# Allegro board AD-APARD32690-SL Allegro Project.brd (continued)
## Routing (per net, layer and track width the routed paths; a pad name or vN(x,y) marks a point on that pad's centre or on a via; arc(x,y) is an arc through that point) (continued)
GND_EARTH: length 68.5
  L2_GND w0.381: P1.1 4.83,41.01 ; P1.1 4.83,38.24 ; P1.1 6.21,39.62 ; P1.1 3.44,39.62
  L3_SIG w0.381: 4.83,38.24 P1.1 ; P1.1 3.44,39.62 ; P1.1 6.21,39.62 ; P1.1 4.83,41.01
  L4_GND w0.381: P1.1 4.83,41.01 ; P1.1 6.21,39.62 ; P1.1 3.44,39.62 ; P1.1 4.83,38.24
  L5_PWR w0.381: 4.83,38.24 P1.1 ; P1.1 3.44,39.62 ; P1.1 4.83,41.01 ; P1.1 6.21,39.62
  L6_PWR w0.381: P1.1 4.83,41.01 ; P1.1 6.21,39.62 ; P1.1 4.83,38.24 ; P1.1 3.44,39.62
  L7_GND w0.381: P1.1 6.21,39.62 ; P1.1 4.83,41.01 ; P1.1 4.83,38.24 ; P1.1 3.44,39.62
  L8_SIG w0.381: 4.83,38.24 P1.1 ; P1.1 3.44,39.62 ; P1.1 6.21,39.62 ; P1.1 4.83,41.01
  L9_GND w0.381: 4.83,38.24 P1.1 ; P1.1 6.21,39.62 ; P1.1 4.83,41.01 ; P1.1 3.44,39.62
  BOTTOM w0.381: P1.1 6.21,39.62 ; P1.1 4.83,41.01 ; P1.1 3.44,39.62 ; P1.1 4.83,38.24 ; C104.2 10.05,40.41 ; C104.2 8.45,41.24 ; C104.2 6.85,40.41 ; C106.2 10.05,50.27 ; C106.2 8.45,49.44 ; C106.2 6.85,50.27
  BOTTOM w0.762: C106.2 v6(8.45,51.5) ; C104.2 v6(8.45,39.18)
  BOTTOM w1.016: C105.2 35.49,36.68 C103.2 35.64,40.59 R147.2
GND_ISO: length 2.5
  TOP w1.016: P11.1 P11.2
VDD_1P1_D: length 108.5
  TOP w0.127: v1(102.17,33.18) 102,33.01 U1.H12
  L8_SIG w0.508: v6(31.18,3.37) 31.69,2.86 40.83,2.86 42.35,4.38 100.01,4.38 102.81,7.18 102.81,24.89 102.17,25.53 v1(102.17,33.18)
  BOTTOM w0.381: 30.23,5.17 C36.1 ; C36.1 31.24,5.17 ; C36.1 30.73,4.64 ; C25.1 103.07,33.18 v1(102.17,33.18) ; 28.94,5.15 C34.2 ; C34.2 30.11,5.15 ; C34.2 29.53,4.61 ; 32.26,3.44 R124.1 31.64,4.01
  vias: v6(30.48,4.06) v6(30.48,3.37) v6(31.18,4.06)
VDD_3P3_D: length 69
  TOP w0.102: 99.31,30.73 U1.B11
  TOP w0.127: U1.D1 100.6,25.41 100.17,24.99 ; 98.95,27.7 U1.A4
  TOP w0.152: 100.3,32.92 100.6,32.62 U1.D12 ; v1(105.09,25.21) 105.09,25.53 104.01,26.61 104.01,26.99 103.65,27.35 U1.M3
  TOP w0.254: C42.1 62.42,45.88 Q4.2 ; v1(97.89,26.64) 98.95,27.7 ; R168.2 v1(62.79,41.08)
  TOP w0.381: 147.51,19.56 C118.1 ; C118.1 148.05,20.07 ; C118.1 148.05,19.05 ; DS4.A v1(62.93,28.08) ; C116.1 146.85,20.07 ; C116.1 146.85,19.05 ; C116.1 147.38,19.56 ; 146.87,17.83 C115.2 ; C115.2 147.41,18.41 ; C115.2 146.87,19 ; C86.1 146.87,21.29 ; C86.1 146.87,20.12 ; C86.1 147.41,20.7 ; C42.1 v1(62.36,46.55) ; S4.3B v1(112.14,1.52) ; S4.2B v1(113.41,1.52) ; 147.48,20.7 C89.1 ; C89.1 148.03,20.12 ; C89.1 148.03,21.29 ; 147.48,18.41 C117.2 ; C117.2 148.03,19 ; C117.2 148.03,17.83 ; v1(100.33,35.05) 100.33,34.55 C27.1 100.33,34.54 100.33,33.43 C70.1 100.3,32.92 ; R126.2 v1(66.29,42.1) ; v6(58.1,33.76) E6.1 ; 100.17,24.99 C20.1 100.2,24.36 C19.2 100.08,23.12 v1(100.08,22.67) ; 114.68,2.48 v1(114.68,1.52) ; JP3.3 v6(138.81,39.45) ; S2.3 v1(118.65,15.28) ; D5.3 v1(119.32,1.97) ; DS2.A v1(127.95,1.91) ; R136.1 v1(130.11,11.24) ; R132.1 v1(65.67,44.97) ; S2.4 v1(128.81,15.28) ; C67.1 98.08,30.73 99.31,30.73 ; R128.1 60.85,33.41 60.14,32.7 v6(59.25,32.7) ; v1(64.96,27.3) 64.96,27.96 DS3.A ; D5.1 v1(121.54,1.97) ; R133.1 v1(131.25,11.24) ; R120.1 v1(111.89,32.35)
  TOP w0.508: v6(141.22,43.69) R141.1 ; v1(65.85,37.65) 65.21,37.65 C69.1 C92.2 ; M1.9 146.9,21.62 ; C21.1 97.32,32.62 ; 97.32,32.62 C67.1 ; 97.32,32.62 v6(97.32,33.3) ; JP4.3 v6(138.42,1.96) ; v6(40.77,4.57) 40.77,4.81 JP2.3 ; M1.10 147.9,21.6 ; v6(141.22,46.23) R142.1
  L2_GND w0.127: 101.41,34.29 101.41,30.48 101.3,30.37 v2(101.3,30.15)
  L2_GND w0.254: v1(102.17,35.05) 101.41,34.29
  BOTTOM w0.254: U2.35 v1(65.85,37.65)
  BOTTOM w0.381: C26.1 103.44,36.17 C75.1 v1(102.17,35.05) ; C74.1 105.5,25.21 v1(105.09,25.21) ; v1(66.29,42.1) 66.04,42.35 R125.2
  BOTTOM w0.508: v1(97.89,26.64) 97.95,26.7 C66.1 C71.1 ; v6(56.13,44.07) 57,44.07 E5.1
  vias: v6(40.89,20.83) v6(40.89,20.19) v6(41.66,20.83) v6(41.66,20.19) v6(110.3,12.64) v6(111,12.64) v6(146.81,17.72) v6(146.81,17.08) v6(147.45,17.72) v6(147.45,17.08) v6(148.08,17.72) v6(148.08,17.08)
VDD_5P0: length 151.5
  TOP w0.254: 49.02,11.05 48.81,11.26 U4.15 ; U3.4 27.5,13.59 v1(27.3,13.4) 27.3,13.14 ; 27.3,13.14 27.36,13.09 U3.5 ; 27.3,13.14 v1(27.3,12.76) 27.48,12.59 U3.6 ; v1(31.5,16.13) 31.5,15.3 31.29,15.09 U3.16 ; U4.9 45.81,11.15 v6(46.04,10.92) 46.31,11.2 U4.10
  TOP w0.381: U9.4 58.49,11.8 ; C127.1 57.08,10.73 ; C127.1 56.55,10.22 ; C127.1 56.55,11.24 ; C126.2 57.12,9.53 ; C126.2 56.57,8.94 ; C126.2 56.57,10.11 ; U9.2 57.19,11.83 ; U9.1 56.54,11.85 ; C112.1 53.59,5.18 ; U9.3 57.84,11.82 ; JP3.1 v6(141.16,37.77) ; v1(58.94,9.15) 58.94,9.91 R170.1
  TOP w0.508: R13.2 v1(46.99,8.38) ; R173.2 58.04,5.33 57.21,6.16 v6(57.21,8.06) ; R16.2 v1(45.85,8.38) ; JP4.1 139.75,3.68 v6(141.1,3.68) ; R14.2 v1(48.13,8.38) ; R15.2 v1(49.28,8.38)
  TOP w0.762: 53.59,5.18 P2.5
  L3_SIG w0.762: v6(141.1,3.68) 140.46,4.32 62.18,4.32 58.43,8.06 v6(57.21,8.06)
  L6_PWR w0.762: v6(141.1,3.68) 139.06,5.71 139.06,33.59 141.16,35.69 v6(141.16,37.77)
  BOTTOM w0.508: v1(31.5,16.13) R17.1
  vias: v6(50.86,10.54) v6(50.86,9.91) v6(51.5,10.54) v6(51.5,9.91) v6(52.13,10.54) v6(52.13,9.91) v6(52.96,6.54) v6(52.96,5.84) v6(56.58,8.7) v6(56.58,8.06) v6(57.21,8.7)
VDD_5P0_INT: length 10.5
  TOP w0.305: 49.31,18.03 49.31,19.61 JP1.1 ; 49.31,18.03 U4.1 ; 49.31,18.03 48.7,18.03 ; U4.2 48.81,17.93 48.7,18.03 ; 48.7,18.03 48.51,18.03 v6(48.32,17.84) 48.31,17.83 U4.3
  TOP w0.508: 21.02,12.19 20.57,11.75
  TOP w0.635: v6(20.57,11.43) v6(20.57,12.19) 21.65,12.19 R1.2 C1.2
  vias: v6(32.07,24.07) v6(32.07,23.43) v6(32.07,22.8) v6(32.7,24.07) v6(32.7,23.43) v6(32.7,22.8) v6(33.34,24.07) v6(33.34,23.43) v6(33.34,22.8) v6(49.21,18.48) v6(49.21,17.84)
VDDA_BB: length 4.8
  TOP w0.381: C29.2 106.61,30.23 v1(105.98,30.23)
  TOP w0.508: C29.2 C31.1
  L2_GND w0.127: v1(105.98,30.23) 104.9,30.23 104.48,29.8 v2(103.05,29.8)
VDDA_RF: length 5.8
  TOP w0.127: U1.M10 104.83,29.8 105.09,30.07
  TOP w0.254: 105.09,30.07 106.08,31.05
  TOP w0.381: 106.08,31.05 107.53,31.05 C30.2
  TOP w0.508: C30.2 C33.1
32KIN: length 6.2
  L2_GND w0.102: v3(103.05,30.15) v2(102.7,29.8)
  L3_SIG w0.089: v1(105.63,29.81) 105.38,29.56 104.01,29.56 103.42,30.15 v3(103.05,30.15)
  BOTTOM w0.127: v1(105.63,29.81) 105.92,29.81 106.24,29.5 106.58,29.5 C45.1 108.12,29.66 Y3.1
32KOUT: length 6.1
  L3_SIG w0.089: v1(105.63,29.31) 103.89,29.31 103.35,29.84 103,29.84 v3(102.7,30.15)
  BOTTOM w0.127: Y3.2 108.09,28.75 C53.1 106.57,28.92 106.01,28.92 v1(105.63,29.31)
ADC_IN0: length 4.5
  TOP w0.127: P3.1 67.88,4.13 68.96,4.13 69.34,4.51 R89.2
ADC_IN1: length 3.5
  TOP w0.127: R110.2 70.87,4.57 P3.2
ADC_IN2: length 3
  TOP w0.127: P3.3 72.39,3.56 R90.2
ADC_IN3: length 2.6
  TOP w0.127: R111.2 P3.4
ADC_IN4: length 2.6
  TOP w0.127: R91.2 P3.5
ADC_IN5: length 2.6
  TOP w0.127: R112.2 P3.6
ADC_IN6: length 2.6
  TOP w0.127: R92.2 P3.7
ADC_IN7: length 2.6
  TOP w0.127: R113.2 P3.8
ADIN1100_TS_TIMER_MS_SEL: length 18
  TOP w0.127: JP5.1 v1(141.17,18.11) ; JP6.1 v1(141.15,5.41)
  L3_SIG w0.089: v1(141.17,18.11) 141.17,5.44 v1(141.15,5.41)
ADIN1110_INT: length 44.7
  TOP w0.127: R56.1 80.74,15.4 v1(80.14,15.4) ; R168.1 61.79,40.33 v1(61.79,41.08)
  L3_SIG w0.089: v1(61.79,41.08) 62.17,40.7 66.23,40.7 67.56,39.37 67.56,17.91 71.06,14.41 79.15,14.41 v1(80.14,15.4)
  BOTTOM w0.127: U2.25 v1(61.79,41.08)
ADIN1110_LINK_ST: length 36.9
  TOP w0.127: v1(83.5,15.4) 84.1,15.4 R22.1
  BOTTOM w0.127: v1(83.5,15.4) 83.09,15.81 68.61,15.81 63.6,20.83 63.6,32.1 62.79,32.9 U2.4
ADIN1110_RESET: length 34.7
  TOP w0.127: v1(78.93,15.4) 80.52,16.99 R55.1
  BOTTOM w0.127: v1(78.93,15.4) 68.39,15.4 63.28,20.51 63.28,31.85 62.29,32.83 U2.5
ADIN1110_SPI_CFG1: length 64.4
  TOP w0.127: v1(112.14,13.53) R166.1
  BOTTOM w0.127: U2.37 66.22,36.65 67.79,35.08 67.79,23.4 72.58,18.61 78.71,18.61 79.63,17.68 83.47,17.68 86.77,14.38 104.55,14.38 105.41,13.53 v1(112.14,13.53)
ADIN1110_TS_CAPT: length 34.5
  TOP w0.127: R49.1 84.17,16.99 v1(83.5,16.99)
  BOTTOM w0.127: U2.40 65.43,35.15 65.6,34.99 65.6,21.84 70.1,17.34 83.15,17.34 v1(83.5,16.99)
ADIN1110_TS_TIMER_MS_SEL: length 33.8
  TOP w0.127: R29.1 v1(80.14,18.41)
  BOTTOM w0.127: U2.30 64.29,40.7 64.42,40.83 65.56,40.83 68.68,37.72 68.68,24.89 74.17,19.4 79.15,19.4 v1(80.14,18.41)
BLE_LDO_1V1: length 35.8
  TOP w0.508: v1(54.99,21.08) 54.98,21.07 JP11.3
  BOTTOM w0.508: E4.2 34.38,6.41 C39.1 35.4,7.54 C38.2 35.38,8.51 35.89,9.02 39.27,9.02 40.29,10.03 42.74,10.03 45.09,12.38 52.32,12.38 53.66,13.72 53.66,19.75 v1(54.99,21.08)
  BOTTOM w0.762: C37.2 34,4.55 E4.2
BLE_LDO_IN: length 90.9
  TOP w0.127: 103.06,31.31 102.7,30.94 U1.K12
  TOP w0.381: v6(103.89,41.59) 105.57,39.91 105.57,35.37 105.19,34.99 103.92,34.99 103.42,34.49 C48.2 103.42,32.85 C51.1 103.41,32.8 103.41,32.77 103.47,32.7 103.47,31.72 103.06,31.31
  TOP w0.508: v6(73.98,38.54) 73.98,25.02 73.28,24.32 69.6,24.32 67.02,21.75 C129.1 JP11.2
  BOTTOM w0.508: v6(73.98,38.54) 73.98,44.32 75.25,45.59 80.9,45.59 83.63,48.32 98.55,48.32 99.57,47.31 99.57,43.75 101.73,41.59 v6(103.89,41.59)
BOOT_LOAD_PDN_O: length 29.9
  L3_SIG w0.089: v3(102.35,29.45) 102.59,29.69 102.83,29.69 102.93,29.59 103.12,29.59 103.7,29.02 105.31,29.02 105.5,28.83 109.09,28.83 111.03,30.77 122.08,30.77 P39.1
BT_ANT: length 20.3
  TOP w0.152: L5.1 115.32,44.27 C41.2 115.26,44.21 115.26,42.67 arc(115.12,41.97) 114.72,41.37 104.42,31.07 arc(103.79,30.65) U1.L12
CAN0B_RX: length 2.5
  TOP w0.127: R84.2 P7.5
CAN0B_TX: length 2.5
  TOP w0.127: R105.2 P7.6
CAN1B_RX: length 2.5
  TOP w0.127: R85.2 P7.7
CAN1B_TX: length 2.5
  TOP w0.127: R106.2 P7.8
FB1: length 7.6
  TOP w0.203: U3.7 28.71,11.64 28.26,11.18 R2.2 R123.1 C1.1 R1.1
FB2: length 10.3
  TOP w0.203: R5.1 C4.1 R6.2 22.73,10.16 23.05,10.48 26.23,10.48 26.48,10.73 28.64,10.73 29.21,11.31 U3.8
FB3: length 7.3
  TOP w0.203: U3.9 29.71,11.04 28.96,10.29 26.75,10.29 26.54,10.08 R7.1 C6.1 24.16,9.64 R8.2
FB4: length 4.6
  TOP w0.203: U3.10 30.21,10.85 29.84,10.48 R11.1 C9.1 R12.2
GPIO1_NINA: length 8.4
  TOP w0.127: P32.1 132.59,22.86 138.78,22.86 138.9,22.73 M1.1
GPIO2_NINA: length 6.8
  TOP w0.127: P33.1 139.78,21.59 139.9,21.72 M1.2
GPIO3_NINA: length 11.6
  TOP w0.127: P34.1 132.78,20.51 134.43,20.51 135.13,21.21 140.46,21.21 140.9,21.65 M1.3
GPIO4_NINA: length 14.6
  TOP w0.127: P35.1 132.65,17.78 132.65,19.56 133.22,20.13 134.56,20.13 135.25,20.83 140.97,20.83 141.9,21.76 M1.4
GPIO5_NINA: length 10.8
  TOP w0.127: M1.5 142.9,21.75 141.6,20.45 135.38,20.45 P36.1
GPIO6_NINA: length 14.9
  TOP w0.127: P40.1 135.38,17.91 135.38,19.56 135.89,20.07 141.99,20.07 143,21.08 144.27,21.08 144.9,21.71 M1.7
GPIO7_NINA: length 11
  TOP w0.127: M1.8 145.86,22.54 145.67,22.35 145.67,21.84 144.4,20.57 143.13,20.57 142.24,19.69 137.29,19.69 P41.1
GPIO16_NINA: length 14.4
  TOP w0.127: P42.1 137.41,36.32 143.38,36.32 147.9,31.8 M1.16
GPIO17_NINA: length 18.2
  TOP w0.127: M1.17 146.9,32.17 143.13,35.94 136.14,35.94 135.51,36.58 135.51,38.61 P43.1
GPIO18_NINA: length 18
  TOP w0.127: P44.1 135.13,38.61 135.13,36.32 135.89,35.56 142.88,35.56 145.9,32.53 M1.18
GPIO24_NINA: length 7.2
  TOP w0.127: M1.24 139.9,31.69 139.71,31.88 135.64,31.88 135.06,31.31 P45.2
GPIO25_NINA: length 5.4
  TOP w0.127: M1.25 136.02,30.8 135.06,29.84 P46.2
GPIO27_NINA: length 18.3
  TOP w0.127: M1.27 138.96,27.69 v1(137.92,27.69)
  L3_SIG w0.089: P47.1 132.84,41.34 132.84,36.58 136.78,32.64 136.78,28.83 v1(137.92,27.69)
GPIO28_NINA: length 16.9
  TOP w0.127: M1.28 138.96,26.67 v1(137.92,26.67)
  L3_SIG w0.089: P48.1 132.46,38.61 132.46,36.45 136.4,32.51 136.4,28.19 v1(137.92,26.67)
GPIO29_NINA: length 15.2
  TOP w0.127: v1(137.92,25.65) 138.95,25.65 M1.29
  L3_SIG w0.089: P49.1 136.02,32.39 136.02,27.56 v1(137.92,25.65)
GPIO31_NINA: length 6.5
  TOP w0.127: P19.2 133.99,23.91 M1.31
GPIO32_NINA: length 6.6
  TOP w0.127: P20.2 v1(134.56,25.46)
  BOTTOM w0.127: v1(134.56,25.46) 135.01,25.01 v1(140.35,25.01)
GPIO34_NINA: length 12.5
  L3_SIG w0.089: P52.1 133.98,35.94 137.16,32.77 137.16,30.41 v1(140.35,27.21)
GPIO35_NINA: length 7
  TOP w0.127: P21.2 v1(134.56,26.92)
  BOTTOM w0.127: v1(134.56,26.92) 135.95,28.31 v1(140.35,28.31)
GPIO36_NINA: length 6.9
  TOP w0.127: M1.36 136.09,29.41 135.06,28.38 P22.2
GPIO_1: length 2.6
  TOP w0.127: R97.2 P4.8
GPIO_2: length 2.5
  TOP w0.127: R77.2 P7.1
GPIO_3: length 2.5
  TOP w0.127: P7.2 R98.2
GPIO_4: length 2.5
  TOP w0.127: R78.2 P7.3
GPIO_5: length 2.5
  TOP w0.127: R99.2 P7.4
GPIO_6: length 3.1
  TOP w0.127: R83.2 P2.3
GPIO_7: length 5.2
  BOTTOM w0.127: R104.2 146.56,13.46 P8.7
GPIO_8: length 1.2
  TOP w0.127: R93.2 P23.2
GPIO_9: length 15.8
  TOP w0.127: P38.1 126.94,38.29 126.94,35.5 122.62,31.18 R94.2
GPIO_10: length 56.2
  TOP w0.127: v1(87.76,9.21) 87.76,14.61 87.38,14.99 R54.1 ; S3.1 131.25,8.09 R133.2 C77.2 v1(132.33,8.83)
  L3_SIG w0.089: v1(132.33,8.83) 129.6,8.83 127.57,6.79 94.3,6.79 93.28,7.81 89.15,7.81 v1(87.76,9.21)
GPIO_11: length 51.8
  TOP w0.127: v1(88.39,9.65) 88.39,14.61 88.77,14.99 R31.1 ; S3.3 130.11,8.09 R136.2 C78.2 v1(129.03,8.83)
  L3_SIG w0.089: v1(88.39,9.65) 89.95,8.1 93.44,8.1 94.42,7.11 127.32,7.11 v1(129.03,8.83)
GPIO_I2C_1: length 2.4
  TOP w0.127: R160.1 P13.1
GPIO_I2C_2: length 2.4
  TOP w0.127: R163.1 P13.2
GPIO_I2C_3: length 5.5
  TOP w0.127: R161.1 146.56,50.04 P13.7
GPIO_I2C_4: length 5.5
  TOP w0.127: R164.1 146.56,47.5 P13.8
GPIO_USR_BTN: length 12.4
  TOP w0.127: R119.1 C57.2 117.85,19.76 R71.1 119.69,19.88 S2.1 S2.2
GPIO_USR_LED1: length 2.9
  TOP w0.127: R74.2 127.06,11.3 R115.1 127.06,8.49 Q1.1
GPIO_USR_LED2: length 2.9
  TOP w0.127: R53.1 119.44,11.3 R117.1 119.44,8.49 Q2.1
GPIO_USR_LED3: length 2.9
  TOP w0.127: R30.1 123.25,11.3 R121.1 123.25,8.49 Q3.1
HFXIN: length 8.6
  TOP w0.127: Y2.1 108.97,25.76 108.36,26.38 107.05,26.38 106.54,25.87 C44.1 105.31,27.04 105.31,27.88 v1(105.12,28.07)
  L2_GND w0.102: v1(105.12,28.07) 105.12,28.32 104.55,28.89 103.61,28.89 v2(103.05,29.45)
HFXOUT: length 6.2
  TOP w0.127: Y2.3 107.82,27.04 107.64,26.86 C52.1 105.95,26.86 105.63,27.18 v1(105.63,28.07)
  L2_GND w0.102: v1(105.63,28.07) 105.38,28.32 105.38,28.45 104.68,29.15 103.7,29.15 v2(103.4,29.45)
HYP_CLK_N: length 42.2
  TOP w0.102: v1(82.59,23.72) 82.31,24 81.6,24 81.22,24.38 81.22,26.27 81.58,26.63 83.27,26.63 83.48,26.83 83.48,29.3 v1(83.18,29.59) 83.48,29.88 83.48,31.13 83.78,31.44 85.67,31.44 85.85,31.62 85.85,32.45 85.03,33.27 82.8,33.27 82.7,33.17 82.7,33.02 v1(82.86,32.87) ; U1.A9 99.2,29.45 99.15,29.5 89.48,29.5 89.29,29.31 89.29,27.63 89,27.34 88.22,27.34 v1(88.07,27.19)
  BOTTOM w0.102: v1(88.07,27.19) 87.67,27.19 87.52,27.34 84.06,27.34 83.2,28.2 83.2,29.58 v1(83.18,29.59) ; U6.B1 81.14,33.23 81.25,33.34 82.38,33.34 v1(82.86,32.87) ; U7.B1 81.33,24.29 82.49,24.29 82.59,24.18 v1(82.59,23.72)
HYP_CLK_P: length 42.2
  TOP w0.102: v1(82.86,33.87) 83.19,33.53 85.13,33.53 86.11,32.55 86.11,31.52 85.77,31.18 83.89,31.18 83.73,31.02 83.73,29.88 v1(84.02,29.59) 83.73,29.3 83.73,26.73 83.37,26.37 81.68,26.37 81.47,26.16 81.47,24.49 81.7,24.26 82.63,24.26 82.74,24.37 82.74,24.57 v1(82.59,24.72) ; U1.A10 99.2,29.8 99.15,29.75 89.38,29.75 89.04,29.41 89.04,27.74 88.9,27.6 88.22,27.6 v1(88.07,27.75)
  BOTTOM w0.102: U6.B2 81.14,33.85 81.41,33.59 82.58,33.59 v1(82.86,33.87) ; v1(82.59,24.72) 82.42,24.54 81.24,24.54 81.14,24.64 U7.B2 ; v1(88.07,27.75) 87.68,27.75 87.52,27.6 84.16,27.6 83.45,28.31 83.45,29.35 83.69,29.59 v1(84.02,29.59)
HYP_CS0_N: length 42
  L3_SIG w0.089: v1(93.34,33.02) 89.98,36.39 89.03,36.39 88.84,36.2 88.84,35.87 88.75,35.78 88.62,35.78 88.54,35.87 88.54,37.66 88.45,37.75 88.32,37.75 88.23,37.66 88.23,35.87 88.14,35.78 88.02,35.78 87.93,35.87 87.93,37.66 87.84,37.75 87.71,37.75 87.62,37.66 87.62,35.87 87.53,35.78 87.41,35.78 87.32,35.87 87.32,37.66 87.23,37.75 87.1,37.75 87.01,37.66 87.01,35.87 86.92,35.78 86.8,35.78 86.71,35.87 86.71,37.66 86.62,37.75 86.49,37.75 86.4,37.66 86.4,35.87 86.31,35.78 86.19,35.78 86.1,35.87 86.1,37.66 86.01,37.75 85.88,37.75 85.79,37.66 85.79,35.87 85.7,35.78 85.58,35.78 85.49,35.87 85.49,37.66 85.4,37.75 85.27,37.75 85.18,37.66 85.18,35.87 85.1,35.78 84.97,35.78 84.88,35.87 84.88,37.66 84.79,37.75 84.67,37.75 84.58,37.66 84.58,35.87 84.49,35.78 84.36,35.78 84.27,35.87 84.27,36.25 84.07,36.45 v1(83.57,36.45)
  BOTTOM w0.102: v1(93.34,33.02) 93.34,31.31 R38.1
  BOTTOM w0.127: U6.A3 83.54,36.45 v1(83.57,36.45)
HYP_CS1_N: length 42
  TOP w0.127: v1(90.69,27.05) 90.69,23.17 90.56,23.04 90.38,23.04 90.25,23.17 90.25,26.48 90.16,26.57 90.02,26.57 89.92,26.48 89.92,23.15 89.83,23.05 89.69,23.05 89.59,23.15 89.59,26.22 89.5,26.32 89.36,26.32 89.26,26.22 89.26,23.15 89.17,23.05 89.03,23.05 88.93,23.15 88.93,25.84 88.84,25.94 88.7,25.94 88.6,25.84 88.6,23.15 88.51,23.05 88.37,23.05 88.27,23.15 88.27,25.39 88.18,25.48 88,25.48 87.91,25.39 87.91,23.16 87.8,23.05 87.64,23.05 87.55,23.14 87.55,24.65 87.44,24.76 87.3,24.76 87.19,24.64 87.19,23.11 87.1,23.02 86.92,23.02 86.8,23.14 86.8,24.32 86.56,24.57 R176.1 84.2,25.07 v1(84.2,25.46)
  BOTTOM w0.127: v1(90.69,27.05) 90.69,27.7 R47.1 ; U7.A3 83.57,26.1 v1(84.2,25.46)
HYP_D0: length 42
  L3_SIG w0.089: v1(78.87,30.54) 78.87,30.29 79.12,30.04 81.47,30.04 81.85,30.42 84.9,30.42 85.03,30.29 85.03,29.44 85.13,29.34 87.51,29.34 87.6,29.25 87.6,28.66 87.69,28.57 87.81,28.57 87.9,28.66 87.9,29.44 87.99,29.53 88.12,29.53 88.21,29.44 88.21,28.66 88.3,28.57 88.42,28.57 88.51,28.66 88.51,29.25 88.6,29.34 88.73,29.34 88.82,29.25 88.82,28.66 88.9,28.57 97.92,28.57 98.09,28.75 v3(100.25,28.75)
  L8_SIG w0.089: v1(78.8,26.42) 78.8,25.43 78.89,25.34 79.05,25.34 79.12,25.41 79.12,26.1 79.25,26.23 79.25,26.8 78.45,27.59 78.45,30.38 78.61,30.54 v1(78.87,30.54) 79.12,30.8 79.12,32.45 79.31,32.64 79.31,33.48 79.18,33.61 78.95,33.61 78.87,33.53 78.87,33.23 78.79,33.15 78.64,33.15 78.54,33.25 78.54,34.04 78.3,34.29 78.3,34.92 78.17,35.05 78.17,35.31 78.29,35.43 v1(78.77,35.43)
  BOTTOM w0.127: U7.D3 78.82,26.42 v1(78.8,26.42) ; U6.D3 v1(78.77,35.43)
HYP_D1: length 42
  L3_SIG w0.089: v1(79.5,30.54) 81.6,30.54 81.79,30.73 85.15,30.73 85.39,30.5 85.39,29.95 85.49,29.84 85.64,29.84 85.74,29.95 85.74,30.45 85.83,30.54 85.95,30.54 86.04,30.45 86.04,29.94 86.13,29.85 86.26,29.85 86.35,29.94 86.35,30.45 86.44,30.54 86.56,30.54 86.65,30.45 86.65,29.94 86.74,29.85 86.87,29.85 86.96,29.94 86.96,30.45 87.05,30.54 87.22,30.54 87.31,30.45 87.31,29.93 87.4,29.84 87.53,29.84 87.62,29.93 87.62,30.52 87.71,30.61 88.14,30.61 89.85,28.89 97.79,28.89 97.92,29.02 100.17,29.02 v3(100.25,29.1)
  L8_SIG w0.089: v1(78.77,34.43) 78.58,34.62 78.58,34.95 78.68,35.05 79.08,35.05 79.18,34.95 79.18,34.68 79.29,34.58 79.56,34.58 79.66,34.47 79.66,34.32 79.57,34.23 79.09,34.23 78.99,34.12 78.99,33.98 79.06,33.91 79.5,33.91 79.63,33.78 79.63,32.45 79.5,32.32 v1(79.5,30.54) 78.93,29.97 78.93,27.5 79.57,26.86 79.57,26.03 79.95,25.65 79.95,25.02 79.81,24.88 79.59,24.88 79.51,24.96 v1(79.51,25.48)
  BOTTOM w0.127: U6.D2 v1(78.77,34.43) ; U7.D2 v1(79.51,25.48)
HYP_D2: length 42
  L3_SIG w0.089: v1(81.34,31.24) 84.45,31.24 85.47,32.26 86.96,32.26 87.05,32.17 87.05,31.39 87.14,31.31 87.26,31.31 87.35,31.39 87.35,32.17 87.44,32.26 87.57,32.26 87.66,32.17 87.66,31.39 87.75,31.31 87.87,31.31 87.96,31.39 87.96,32.17 88.05,32.26 88.18,32.26 88.26,32.17 88.26,31.39 88.35,31.31 88.48,31.31 88.57,31.39 88.57,32.17 88.66,32.26 88.9,32.26 89.15,32 89.15,30.67 90.3,29.53 97.66,29.53 97.92,29.27 99.57,29.27 99.74,29.45 v3(100.25,29.45)
  L8_SIG w0.089: v1(80.51,27.48) 80.51,27.47 80.51,27.19 81.03,26.67 81.5,26.67 81.6,26.77 81.6,26.98 81.53,27.05 81.22,27.05 80.96,27.3 80.96,27.97 81.06,28.08 81.48,28.08 81.66,28.26 81.66,30.92 v1(81.34,31.24) 81.09,31.5 81.09,34.73 81.47,35.12 81.47,35.75 81.03,36.2 81.03,36.92 80.92,37.02 80.61,37.02 80.52,36.93 v1(80.52,36.43)
  BOTTOM w0.127: U6.C4 v1(80.52,36.43) ; U7.C4 v1(80.51,27.48)
HYP_D3: length 42
  L2_GND w0.102: v3(98.62,30.42) 98.93,30.73 99.31,30.73 v2(100.25,29.8)
  L3_SIG w0.089: v1(80.33,32.39) 80.33,32.89 80.64,33.21 80.84,33.21 80.9,33.15 80.9,32.51 80.96,32.45 81.09,32.45 81.15,32.51 81.15,33.21 81.53,33.59 81.72,33.59 81.79,33.53 81.79,33.15 81.85,33.08 82.02,33.08 82.11,33.17 82.11,34.23 82.74,34.86 83.06,34.86 83.38,34.54 83.63,34.54 83.95,34.86 89.73,34.86 94.04,30.54 98.49,30.54 v3(98.62,30.42)
  L8_SIG w0.089: v1(79.51,27.48) 79.28,27.71 79.28,27.9 79.38,28 79.95,28 80.96,29.02 80.96,30.29 80.84,30.41 80.73,30.41 80.64,30.33 80.64,30.14 80.54,30.04 80.4,30.04 80.33,30.11 v1(80.33,32.39) 80.33,34.86 80.07,35.12 80.07,35.43 79.25,36.26 79.25,36.7 79.41,36.86 79.72,36.86 79.82,36.97 79.82,37.11 79.72,37.21 79.18,37.21 78.77,36.79 v1(78.77,36.43)
  BOTTOM w0.127: U6.D4 v1(78.77,36.43) ; U7.D4 v1(79.51,27.48)
HYP_D4: length 42
  L2_GND w0.102: v3(97.51,29.21) 97.97,28.75 v2(99.9,28.75)
  L3_SIG w0.089: v1(79.95,31.24) 80.33,30.86 81.53,30.86 81.66,30.99 85.22,30.99 85.28,31.05 85.28,31.62 85.34,31.69 85.47,31.69 85.53,31.62 85.53,30.92 85.6,30.86 85.72,30.86 85.81,30.95 85.81,31.92 85.9,32.01 86.03,32.01 86.12,31.92 86.12,30.95 86.21,30.86 86.33,30.86 86.42,30.95 86.42,31.92 86.51,32.01 86.64,32.01 86.73,31.92 86.73,31.08 86.82,30.99 88.33,30.99 90.11,29.21 v3(97.51,29.21)
  L8_SIG w0.089: v1(78.77,37.43) 78.77,37.43 78.33,36.99 78.33,36.35 78.68,36 78.99,36 79.69,35.31 79.69,34.99 79.95,34.73 v1(79.95,31.24) 79.95,29.43 80.01,29.37 80.16,29.37 80.26,29.47 80.26,29.68 80.37,29.78 80.54,29.78 80.64,29.68 80.64,29.15 80.54,29.05 79.73,29.05 79.63,29.15 79.63,29.9 79.53,30 79.38,30 79.25,29.88 79.25,28.74 v1(79.51,28.48)
  BOTTOM w0.127: U6.D5 v1(78.77,37.43) ; U7.D5 v1(79.51,28.48)
HYP_D5: length 42
  L2_GND w0.102: v3(98.55,29.65) 99.11,29.1 v2(99.9,29.1)
  L3_SIG w0.089: v3(98.55,29.65) 98.04,29.65 97.85,29.84 93.03,29.84 91.5,31.37 91.5,32 89.66,33.85 86.04,33.85 84.07,31.88 80.84,31.88 80.58,31.62 79.69,31.62 79.12,31.05 78.61,31.05 78.04,30.48 77.47,30.48 v1(77.22,30.73)
  L8_SIG w0.089: v1(77.77,35.43) 77.16,35.43 77.03,35.56 77.03,35.84 76.92,35.94 76.52,35.94 76.42,35.84 76.42,31.53 v1(77.22,30.73) 77.22,29.59 76.93,29.31 76.93,25.08 77.03,24.98 77.18,24.98 77.29,25.09 77.29,25.57 77.44,25.72 v1(77.76,25.72)
  BOTTOM w0.127: U6.E3 v1(77.77,35.43) ; U7.E3 v1(77.76,25.72)
HYP_D6: length 42
  L2_GND w0.102: v3(98.84,29.91) 99.3,29.45 v2(99.9,29.45)
  L3_SIG w0.089: v1(78.68,31.56) 79.18,31.56 79.57,31.94 80.45,31.94 80.64,32.13 83.82,32.13 84.07,32.39 84.07,34.14 84.16,34.23 84.43,34.23 84.52,34.14 84.52,33.63 84.62,33.53 84.8,33.53 84.9,33.63 84.9,34.14 84.99,34.23 89.85,34.23 93.92,30.16 97.98,30.16 98.23,29.91 v3(98.84,29.91)
  L8_SIG w0.089: v1(78.51,24.72) 78.51,26.07 78.14,26.45 78.14,30.64 78.68,31.18 v1(78.68,31.56) 78.23,32 78.23,33.85 77.98,34.1 77.98,34.77 77.82,34.92 77.03,34.92 76.9,34.8 76.9,34.23 77,34.13 77.18,34.13 77.28,34.23 77.28,34.48 77.35,34.55 77.52,34.55 77.6,34.48 77.6,33.85 v1(77.77,33.67)
  BOTTOM w0.127: U6.E2 v1(77.77,33.67) ; U7.E2 v1(78.51,24.72)
HYP_D7: length 42
  L2_GND w0.102: v3(99.12,30.42) 99.74,29.8 v2(99.9,29.8)
  L3_SIG w0.089: v1(77.77,30.99) 77.77,31.67 78.11,32 79.06,32 80.58,33.53 81.03,33.53 82.61,35.12 90.04,35.12 94.3,30.86 98.68,30.86 v3(99.12,30.42)
  L8_SIG w0.089: v1(77.76,24.48) 77.76,24.86 78.2,25.3 78.2,25.88 77.34,26.73 77.34,29.15 77.77,29.57 v1(77.77,30.99) 77.77,31.39 77.67,31.5 76.94,31.5 76.83,31.6 76.83,31.75 76.94,31.85 77.82,31.85 77.93,31.95 77.93,32.09 77.82,32.19 76.94,32.19 76.83,32.3 76.83,33.62 76.94,33.72 77.11,33.72 77.22,33.62 77.22,32.83 77.37,32.67 v1(77.77,32.67)
  BOTTOM w0.127: U6.E1 v1(77.77,32.67) ; U7.E1 v1(77.76,24.48)
HYP_RSTN: length 42
  L3_SIG w0.089: v1(82.04,30.04) 82.04,29.15 82.61,28.57 83.76,28.57 84.24,28.09 84.24,26.44 84.33,26.35 84.46,26.35 84.55,26.44 84.55,28.47 84.63,28.56 84.76,28.56 84.85,28.47 84.85,26.44 84.94,26.35 85.07,26.35 85.15,26.44 85.15,28.47 85.24,28.56 85.37,28.56 85.46,28.47 85.46,26.44 85.55,26.35 85.67,26.35 85.76,26.44 85.76,28.47 85.85,28.56 85.98,28.56 86.07,28.47 86.07,26.44 86.16,26.35 86.28,26.35 86.37,26.44 86.37,28.47 86.46,28.56 86.64,28.56 86.74,28.46 v1(86.74,25.27)
  L8_SIG w0.089: v1(82.52,36.43) 82.93,36.02 82.93,35.43 82.74,35.24 82.23,35.24 82.04,35.05 v1(82.04,30.04) 82.3,29.78 82.3,29.59 82.04,29.34 82.04,29.18 82.14,29.08 82.68,29.08 82.74,29.02 82.74,28.8 82.68,28.74 82.11,28.74 82.04,28.67 82.04,28.44 82.11,28.38 82.66,28.38 82.74,28.3 82.74,28.15 82.65,28.07 82.11,28.07 82.04,28 82.04,27.05 82.17,26.92 82.74,26.92 82.81,27 82.81,27.4 82.74,27.48 v1(82.51,27.48)
  BOTTOM w0.127: R18.1 v1(86.74,25.27) ; U6.A4 v1(82.52,36.43) ; U7.A4 v1(82.51,27.48)
HYP_RWDS: length 42
  L3_SIG w0.089: v1(89.66,31.05) 89.66,32 89.85,32.19 90.2,32.19 90.3,32.09 90.3,30.02 90.41,29.91 90.69,29.91 90.8,30.02 90.8,32.19 90.36,32.64 86.21,32.64 86.11,32.75 86.11,32.89 86.21,32.99 89.56,32.99 89.66,33.09 89.66,33.24 89.56,33.34 86.04,33.34 84.33,31.62 81.09,31.62 v1(80.71,31.24)
  L8_SIG w0.089: v1(80.51,26.48) 80.52,26.47 80.52,26.16 80.39,26.04 80.07,26.04 79.91,26.19 79.91,26.57 80.14,26.8 80.14,27.05 79.95,27.24 79.95,27.56 81.34,28.96 81.34,30.42 81.03,30.73 80.84,30.73 80.71,30.86 v1(80.71,31.24) 80.71,34.8 81.15,35.24 81.15,35.69 80.96,35.88 80.55,35.88 80.12,36.31 79.99,36.31 79.88,36.19 79.88,36.07 v1(80.52,35.43)
  BOTTOM w0.127: U6.C3 v1(80.52,35.43) ; v1(89.66,31.05) 90.61,31.05 R65.1 ; U7.C3 v1(80.51,26.48)
I2C0A_SCL: length 37.7
  TOP w0.127: P13.9 P13.3 R142.2 142.99,45.46 142.75,45.21 130.43,45.21 125.63,40.42 125.63,37.62 121.28,33.27 118.62,33.27 118.17,33.72 R32.1
I2C0A_SDA: length 37.6
  TOP w0.127: P13.10 P13.4 R141.2 142.99,44.46 142.75,44.7 130.49,44.7 125.98,40.2 125.98,37.47 121.41,32.89 118.62,32.89 118.17,32.45 R57.1
I2C1A_SCL: length 3.7
  TOP w0.127: P5.1 R144.1 34.37,48.3 R103.2
I2C1A_SDA: length 3.7
  TOP w0.127: P5.2 R143.1 36.91,48.3 R82.2
IO_REF_ARD: length 59.4
  TOP w0.508: JP2.2 45.28,6.16 ; C108.1 45.97,5.18 ; v6(36.83,46.67) R143.2 ; v6(34.29,46.67) R144.2
  TOP w0.584: C108.1 46.07,6.52 C107.2
  TOP w0.762: 45.97,5.18 P2.2
  L3_SIG w0.889: v6(45.34,5.84) v6(45.34,6.54) 44.2,7.68 44.2,28.26 45.78,29.84 45.78,40.7 39.81,46.67 v6(36.83,46.67) v6(34.29,46.67)
LT8692S_1P1: length 14.5
  TOP w0.508: R11.2 C9.2 28.76,8.64 C17.2 28.74,7.22 C100.1 31.62,6.16 32.36,5.42 E3.1
  TOP w0.889: E3.1 34.23,5.42 35.05,4.6
  TOP w1.016: C7.2 35.05,8.49 L1.2
LT8692S_1P8: length 20.5
  TOP w0.508: C98.1 26.52,7.21 C16.2 v6(26.54,7.94) R7.2 C6.2
  BOTTOM w0.381: v6(40.64,12.26) 40.32,12.26 38.54,10.48 29.08,10.48 v6(26.54,7.94) v6(25.46,7.94)
  vias: v6(40.64,13.53) v6(40.64,12.89) v6(41.27,13.53) v6(41.27,12.89) v6(41.27,12.26) v6(41.91,13.53) v6(41.91,12.89) v6(41.91,12.26)
LT8692S_3P3: length 26.6
  TOP w0.508: C96.1 20.59,7.21 C95.2 v6(20.57,7.94) R5.2 C4.2
  BOTTOM w0.381: v6(20.57,7.94) v6(21.65,7.94) 22.92,9.21 25.91,9.21 28.38,11.68 37.15,11.68 v6(40.64,15.18)
  vias: v6(40.64,16.45) v6(40.64,15.81) v6(41.27,16.45) v6(41.27,15.81) v6(41.27,15.18) v6(41.91,16.45) v6(41.91,15.81) v6(41.91,15.18)
LT8692S_PG: length 17.6
  TOP w0.127: v1(29.01,3.3) 29.01,2.04 29.1,1.95 DS1.A
  TOP w0.254: U3.19 v1(29.21,16.89)
  L3_SIG w0.089: v1(29.21,16.89) 28.32,15.99 28.32,3.99 v1(29.01,3.3)
  BOTTOM w0.254: v1(29.21,16.89) 29.21,16.13 R17.2
MCU_RESET_N: length 19.7
  TOP w0.127: P9.10 120.14,30.35 114.38,30.35 S1.1 114.06,30.68 R120.2 C55.2 110.62,30.55 v1(110.62,29.72)
  L3_SIG w0.089: v3(102.7,29.45) 102.81,29.34 103,29.34 103.57,28.77 105.19,28.77 105.41,28.54 109.44,28.54 v1(110.62,29.72)
OWM_IO: length 10.5
  TOP w0.127: P6.4 R21.1 68.72,48.38 68.06,48.38 67.75,48.07 67.75,44.45 66.98,43.68 R126.1 66.18,43.56 P18.1
OWM_PE: length 7.1
  TOP w0.127: P6.3 R48.1 66.18,48.38 65.52,48.38 65.21,48.07 65.21,46.16 R132.2 65.02,45.9 65,45.88 Q4.1
PI+: length 37.8
  TOP w0.102: R155.2 18.87,35.05 18.77,34.95 18.77,34.58 18.67,34.48 17.59,34.48 15.37,36.7 15.37,44.01 13.91,45.47 11.72,45.47 11.62,45.57 P16.2 P16.1
  BOTTOM w0.102: P1.3 4.83,45.59 4.95,45.47 6.99,45.47 7.18,45.66 7.18,46.77 7.68,47.27 C106.1 9.22,47.27 9.72,46.77 9.72,45.69 9.94,45.47 10.73,45.47 10.86,45.59 10.86,46.29 P16.2 12.38,46.29 12.38,45.62 12.53,45.47 13.78,45.47 13.91,45.59 D8.1
PI-: length 37.8
  TOP w0.102: P17.1 P17.2 11.62,45.11 11.72,45.21 13.8,45.21 15.11,43.9 15.11,36.6 17.48,34.23 18.67,34.23 18.77,34.12 18.77,33.76 18.87,33.66 R156.2
  BOTTOM w0.102: D8.2 13.91,45.08 13.78,45.21 12.53,45.21 12.38,45.06 12.38,44.39 P17.2 10.86,44.39 10.86,45.08 10.73,45.21 9.94,45.21 9.72,44.99 9.72,43.91 9.22,43.41 C104.1 7.68,43.41 7.18,43.91 7.18,45.02 6.98,45.21 4.95,45.21 4.83,45.08 P1.2
QSPI_SCK: length 24.4
  TOP w0.127: U5.6 96.69,10.95 95.06,12.57 95.06,17.94 95.98,18.86 100.87,18.86 103.38,21.37 103.38,24.99 102.35,26.02 U1.J1
QSPI_SDIO0: length 25.9
  TOP w0.127: U5.5 96.81,9.68 94.42,12.07 v1(94.42,17.65)
  L2_GND w0.102: v3(102.55,23.34) 102.54,23.35 102.54,26.56 102.35,26.75 v2(102.35,27)
  L3_SIG w0.089: v3(102.55,23.34) 102.55,20.83 99.38,17.65 v1(94.42,17.65)
QSPI_SDIO1: length 23.1
  TOP w0.127: U5.2 92.29,12.22 92.71,12.64 v1(92.71,17.65)
  L2_GND w0.102: v3(100.65,23.88) 100.65,25.08 102,26.43 v2(102,27)
  L3_SIG w0.089: v3(100.65,23.88) 99.66,22.89 99.66,20.29 98.62,19.24 96.04,19.24 95.22,18.41 92.9,18.41 92.71,18.22 v1(92.71,17.65)
QSPI_SDIO2: length 25.3
  TOP w0.127: v1(93.28,17.65) 93.28,12.09 92.14,10.95 U5.3
  L3_SIG w0.089: v1(93.28,17.65) 93.66,18.03 99.31,18.03 101.73,20.45 101.73,24.23 102.35,24.85 v3(102.35,27.35)
QSPI_SDIO3: length 20
  TOP w0.127: U5.7 96.96,12.22 96.71,12.47 v1(96.71,18.41)
  L3_SIG w0.089: v3(102,27.35) 102,24.91 101.47,24.38 101.47,20.64 99.25,18.41 v1(96.71,18.41)
QSPI_SS0: length 23.5
  TOP w0.127: U5.1 91.85,13.49 92.27,13.91 92.27,17.91 92.55,18.19 94.71,18.19 95.82,19.3 100.87,19.3 103.06,21.49 103.06,24.86 102,25.92 U1.H1
RESET_NINA: length 17.6
  TOP w0.127: M1.19 144.9,31.88 142.11,34.67 132.4,34.67 131.95,34.23 R114.2
RXN: length 3.7
  BOTTOM w0.102: U2.13 57.23,36.15 57.02,35.95 57.02,35.91 ; 57.02,35.91 56.67,36.26 56.35,36.26 R146.1 ; 57.02,35.91 R135.1
RXP: length 3.7
  TOP w0.102: v1(57.79,36.65) 57.55,36.89 R129.1 56.98,36.89 56.61,36.51 56.32,36.51 55.94,36.9 R140.1
  BOTTOM w0.102: U2.14 v1(57.79,36.65)
SHIELD: length 23.7
  TOP w0.508: C123.2 10.1,31.57
  TOP w0.635: P10.GND1 7.17,31.62 R145.1 9.52,33.66 10.1,33.08 10.1,31.57
  BOTTOM w1.016: P10.GND1 P10.GND3 P10.GND4 P10.GND2
SPI0_MISO: length 59
  TOP w0.127: v1(128.02,22.61) 128.27,22.61 131.89,26.23 131.89,27.69 132.59,28.38 P22.1 ; P4.3 R107.2 95.07,5.09 v1(95.69,5.09)
  BOTTOM w0.127: v1(128.02,22.61) 126.94,22.61 126.49,22.16 126.49,8.95 124.21,6.67 101.92,6.67 100.9,5.65 97.98,5.65 97.42,5.09 v1(95.69,5.09)
SPI0_MOSI: length 55.2
  TOP w0.127: P21.1 132.59,26.92 132.21,26.54 132.21,26.04 128.27,22.1 v1(127.06,22.1) ; R87.2 97.54,5.09 ; 97.54,5.09 P4.4 ; 97.54,5.09 v1(98.23,5.09)
  BOTTOM w0.127: v1(127.06,22.1) 126.87,21.91 126.87,8.83 124.33,6.29 102.11,6.29 100.91,5.09 v1(98.23,5.09)
SPI0_SCK: length 58.3
  TOP w0.127: P4.2 R108.2 92.53,5.09 v1(93.15,5.09) ; v1(126.05,21.21) 128.4,21.21 131.19,24 P19.1
  BOTTOM w0.127: v1(126.05,21.21) 126.05,9.02 124.08,7.05 101.66,7.05 100.71,6.1 97.85,6.1 97.35,5.59 95.44,5.59 94.94,5.09 v1(93.15,5.09)
SPI0_SDIO2: length 53.1
  TOP w0.127: R88.2 102.62,5.09 ; 102.62,5.09 v1(103.31,5.09) ; 102.62,5.09 P4.6 ; v1(132.46,29.84) P46.1
  BOTTOM w0.127: v1(132.46,29.84) 132.46,25.91 127.63,21.08 127.63,8.45 124.71,5.52 103.76,5.52 103.32,5.09 v1(103.31,5.09)
SPI0_SDIO3: length 52.7
  TOP w0.127: v1(132.46,31.31) P45.1 ; P4.7 105.16,5.09 ; 105.16,5.09 v1(105.85,5.09) ; 105.16,5.09 R109.2
  BOTTOM w0.127: v1(105.85,5.09) 124.85,5.09 128.02,8.25 128.02,20.89 132.91,25.78 132.91,30.16 132.46,30.61 v1(132.46,31.31)
SPI0_SS1: length 2.6
  TOP w0.127: R86.2 P4.1
SPI1A_MISO: length 2.5
  TOP w0.127: R45.1 P5.6
SPI1A_MOSI: length 2.5
  TOP w0.127: R72.1 P5.7
SPI1A_SCLK: length 2.5
  TOP w0.127: R44.1 P5.5
SPI1A_SDIO2: length 2.5
  TOP w0.127: R46.1 P5.9
SPI1A_SDIO3: length 2.5
  TOP w0.127: R73.1 P5.10
SPI1A_SS0: length 2.5
  TOP w0.127: R69.1 P5.8
SPI1A_SS1: length 2.5
  TOP w0.127: R70.1 P6.1
SPI1A_SS2: length 2.5
  TOP w0.127: R43.1 P6.2
SPI2_MISO_MAXQ1065: length 3.3
  TOP w0.127: R75.2 108.14,18.25 107.79,17.91 107.12,17.91 106.56,17.34 U8.4
SPI2_MOSI_MAXQ1065: length 4.1
  TOP w0.127: R96.2 109.54,18.25 108.87,17.59 107.51,17.59 107.06,17.14 U8.3
SPI2_SCK_MAXQ1065: length 5
  TOP w0.127: U8.2 107.56,17.01 107.82,17.27 110.17,17.27 110.93,18.03 R95.2
SPI2A_SS0_MAXQ1065: length 2.5
  TOP w0.127: U8.5 106.06,17.57 106.74,18.25 R76.2
SPI3A_MISO_ADIN1110: length 92.6
  TOP w0.127: R167.1 v1(113.41,13.53)
  L2_GND w0.102: v2(100.25,27.35) v3(99.12,26.23)
  L3_SIG w0.089: v3(99.12,26.23) 99.12,26.04 95.88,22.8 90.96,22.8 85.6,17.43 79.79,17.43 v1(78.93,16.57)
  BOTTOM w0.127: v1(113.41,13.53) 113.03,13.14 105.22,13.14 104.3,14.07 86.3,14.07 84.14,16.22 82.01,16.22 81.66,16.57 v1(78.93,16.57) 69.21,16.57 64.04,21.75 64.04,32.67 63.79,32.92 U2.2
SPI3A_MOSI_ADIN1110: length 54.2
  TOP w0.102: U1.B2 99.5,26.61
  TOP w0.127: v1(82.8,16.99) 83.5,17.68 88.49,17.68 94.49,23.69 96.52,23.69 99.44,26.61 99.5,26.61
  BOTTOM w0.127: U2.1 64.29,33.06 64.45,32.89 64.45,22.13 69.6,16.99 v1(82.8,16.99)
SPI3A_SCLK_ADIN1110: length 55.1
  TOP w0.127: v1(82.8,18.41) 82.07,17.68 v1(78.93,17.68)
  L2_GND w0.102: v3(98.68,26.67) 98.87,26.86 99.25,26.86 99.74,27.35 v2(99.9,27.35)
  L3_SIG w0.089: v1(82.8,18.41) 83.28,17.94 85.41,17.94 91.03,23.56 95.88,23.56 98.58,26.26 98.58,26.57 v3(98.68,26.67)
  BOTTOM w0.127: v1(78.93,17.68) 70.71,17.68 66.17,22.23 66.17,35.75 65.77,36.15 U2.38
SPI3A_SS0_ADIN1110: length 37.4
  TOP w0.127: R24.1 v1(83.5,18.41)
  BOTTOM w0.127: U2.29 63.79,40.8 64.26,41.28 66.29,41.28 69.6,37.97 69.6,26.32 75.76,20.16 81.76,20.16 v1(83.5,18.41)
SPI4A_MISO: length 2.2
  TOP w0.127: JP8.3 135.26,8.81 135.25,8.83 R59.1
SPI4A_MOSI: length 4.6
  TOP w0.127: R33.1 135.25,11.37 135.26,11.35 JP7.3
SPI4A_SCLK: length 4.6
  TOP w0.127: R34.1 135.25,6.29 135.26,6.27 JP10.3
SPI4A_SDIO2: length 2.2
  TOP w0.127: JP6.3 135.26,3.73 135.25,3.75 R60.1
SPI4A_SDIO3: length 5.2
  BOTTOM w0.127: R35.1 146.56,8.38 P8.10
SPI4A_SS0: length 2.2
  TOP w0.127: R58.1 135.25,13.91 135.26,13.89 JP9.3
SPI4A_SS1: length 2.4
  TOP w0.127: R61.1 137.79,17.21 138.56,16.43 JP5.3
SWPD_EN: length 67.6
  TOP w0.127: v1(114.68,13.53) R138.1
  BOTTOM w0.127: v1(114.68,13.53) 114.24,13.97 105.54,13.97 104.81,14.7 87,14.7 83.69,18 79.88,18 78.9,18.99 74.17,18.99 68.23,24.92 68.23,36.35 65.93,38.65 U2.33
TCK: length 2.7
  TOP w0.127: R159.1 P9.4
TDO: length 60.8
  TOP w0.127: P20.1 132.14,25.46 128.33,21.65 v1(127.57,21.65) 126.75,21.65 125.98,22.42 R20.1
  BOTTOM w0.127: v1(127.57,21.65) 127.25,21.34 127.25,8.64 124.52,5.91 102.3,5.91 100.08,3.68 P4.5
TMS: length 2.7
  TOP w0.127: R162.1 P9.2
TRX_N: length 21.2
  TOP w0.102: R134.2 54.94,35.87 54.55,36.26 54.17,36.26 v1(54.01,36.1) 53.85,36.26 53.47,36.26 53.37,36.16 D9.1 52.86,35.53 52.76,35.63 52.76,36.16 52.66,36.26 50.86,36.26 50.67,36.07 50.67,35.34 P15.1 49.34,35.34 49.34,36.07 49.15,36.26 47.25,36.26 47.15,36.16 C99.1 47.01,35.38 46.12,36.27 45.79,36.27 45.59,36.07 T1.2 44.19,36.07 44,36.27 43.51,36.27 43.05,36.72 43.05,37.4 42.91,37.55 v1(42.91,37.82)
  BOTTOM w0.102: v1(42.91,37.82) 42.91,37.35 42.36,36.81 R151.1 ; v1(54.01,36.1) 54.17,36.26 54.58,36.26 54.94,35.9 R146.2
TRX_P: length 20.8
  TOP w0.102: R140.2 54.94,36.87 54.58,36.51 54.17,36.51 v1(54.01,36.67) 53.85,36.51 53.47,36.51 53.37,36.61 D2.1 52.86,37.24 52.76,37.14 52.76,36.61 52.66,36.51 50.86,36.51 50.67,36.7 50.67,37.43 P12.1 49.34,37.43 49.34,36.7 49.15,36.51 47.25,36.51 47.15,36.61 C97.2 46.98,37.39 46.11,36.52 45.77,36.52 45.58,36.72 T1.1 44.18,36.72 43.98,36.52 43.62,36.52 43.31,36.83 43.31,37.4 43.47,37.56 v1(43.47,37.82)
  BOTTOM w0.102: R148.1 44,36.81 43.47,37.34 v1(43.47,37.82) ; R131.2 54.94,36.84 54.61,36.51 54.17,36.51 v1(54.01,36.67)
TXN: length 3.7
  TOP w0.102: v1(57.79,35.65) 57.55,35.89 R129.2 56.65,36.26 56.32,36.26 55.94,35.87 R134.1
  BOTTOM w0.102: U2.12 v1(57.79,35.65)
TXP: length 3.7
  BOTTOM w0.102: R131.1 56.35,36.51 56.64,36.51 57.02,36.89 R135.2 57.02,36.95 57.23,37.15 U2.15
UART0_RX: length 2.6
  TOP w0.127: R79.2 P9.8
UART0_TX: length 2.6
  TOP w0.127: R100.2 P9.6
UART1A_CTS: length 119.7
  TOP w0.127: JP10.1 v1(133.6,7.95) ; P6.6 R80.2 73.99,48.38 v1(74.67,48.38)
  L3_SIG w0.089: v1(71.88,10.29) 72.71,11.11 90.87,11.11 94.55,7.43 126.49,7.43 128.33,9.27 133.86,9.27 134.24,8.89 134.24,8.57 133.62,7.95 v1(133.6,7.95)
  L8_SIG w0.089: v1(71.88,10.29) 73.02,11.43 73.02,14.54 68.9,18.67 68.9,24.83 71.63,27.56 71.63,47.5 72.07,47.94 72.33,47.94 72.76,48.38 v1(74.67,48.38)
UART1A_RTS: length 118.1
  TOP w0.127: P6.5 R81.2 71.45,48.38 v1(72.13,48.38) ; v1(133.6,14.61) 134.87,14.61 135.84,15.57 JP9.1
  L3_SIG w0.089: v1(71.88,10.86) 72.45,11.43 91,11.43 94.68,7.75 126.36,7.75 128.21,9.59 133.29,9.59 134.37,10.67 134.37,11.81 134.05,12.13 134.05,14.16 v1(133.6,14.61)
  L8_SIG w0.089: v1(72.13,48.38) 71.37,47.62 71.37,27.75 68.58,24.96 68.58,18.54 72.71,14.41 72.71,11.68 v1(71.88,10.86)
UART1A_RX: length 117.4
  TOP w0.127: P6.7 R101.2 76.53,48.38 v1(77.21,48.38) ; JP8.1 v1(133.6,10.49)
  L3_SIG w0.089: v1(71.88,11.49) 72.14,11.75 91.12,11.75 94.81,8.06 126.24,8.06 128.08,9.91 133.02,9.91 v1(133.6,10.49)
  L8_SIG w0.089: v1(71.88,11.49) 72.33,11.94 72.33,14.29 68.26,18.35 68.26,25.15 71.06,27.94 71.06,47.88 71.95,48.77 76.83,48.77 77.21,48.39 v1(77.21,48.38)
UART1A_TX: length 124.3
  TOP w0.127: P6.8 R102.2 79.07,48.38 v1(79.75,48.38) ; JP7.1 138.57,13.03 137.67,12.13 v1(133.6,12.13)
  L3_SIG w0.089: v1(133.6,12.13) 134.05,11.68 134.05,11.11 133.86,10.92 133.48,10.92 132.78,10.22 127.95,10.22 126.11,8.38 94.93,8.38 91.25,12.07 v1(71.88,12.07)
  L8_SIG w0.089: v1(79.75,48.38) 77.8,48.38 77.09,49.09 71.75,49.09 70.74,48.07 70.74,28.13 67.94,25.34 67.94,18.16 71.88,14.22 v1(71.88,12.07)
UART2A_CTS: length 16.8
  TOP w0.127: M1.20 143.9,31.86 141.6,34.16 132.4,34.16 131,32.77 R36.1
UART2A_RTS: length 16
  TOP w0.127: R62.1 130.11,31.31 132.46,33.66 141.1,33.66 142.9,31.85 M1.21
UART2A_RX: length 15.7
  TOP w0.127: R37.1 130.18,29.84 131.25,30.92 131.25,31.88 132.46,33.08 140.72,33.08 141.9,31.9 M1.22
UART2A_TX: length 15.6
  TOP w0.127: R63.1 130.18,28.38 131.64,29.84 131.64,31.69 132.59,32.64 140.4,32.64 140.9,32.13 M1.23
UNNAMED_2_ADLT3040_I358_FAULTN: length 1.5
  TOP w0.381: R170.2 59.14,11.13 U9.5
UNNAMED_2_ADLT3040_I358_FS: length 12.2
  TOP w0.381: U9.7 59.79,16.93 60.33,17.47 C124.2 60.32,18.11 R169.1 R175.2
  TOP w0.508: R174.2 65.21,18.61 64.52,19.3 R169.1
UNNAMED_2_ADLT3040_I358_ILIM: length 1.5
  TOP w0.381: R171.2 59.79,11.13 U9.6
UNNAMED_2_ADLT3040_I358_OUT1: length 1.7
  TOP w0.381: C128.2 57.18,18.1 ; C128.2 56.63,17.51 ; C128.2 56.63,18.68
UNNAMED_2_ADLT3040_I358_VIN: length 2.9
  TOP w0.381: R169.2 59.28,19.27 C125.2 59.28,17.43 59.14,17.29 U9.8
UNNAMED_2_ADLT8692S_I193_EN: length 8.5
  TOP w0.127: C3.2 26.08,15.09 U3.1
  TOP w1.016: F3.2 D1.C
  BOTTOM w0.508: R3.2 v6(24.83,15.11) D4.C
UNNAMED_2_ADLT8692S_I193_EN1: length 2.8
  TOP w0.254: U3.3 v1(27.31,14.09)
  BOTTOM w0.381: 28.06,13.97 27.94,14.09 v1(27.31,14.09)
  BOTTOM w0.635: R3.1 28.06,15.05 28.06,13.97 28.07,13.96 R4.1
UNNAMED_2_ADLT8692S_I193_INTVCC: length 3
  TOP w0.254: U3.11 31.22,12.59 31.4,12.41 31.4,10.38 C5.1
UNNAMED_2_ADLT8692S_I193_SW4: length 6.2
  TOP w0.254: 32.32,12.57 31.3,13.59 U3.13
  TOP w0.762: L1.1 33.04,9.95 32.32,10.67 32.32,12.57
UNNAMED_2_CAP_I379_N1: length 10.9
  TOP w0.305: U10.2 63.56,6.63 C130.1 ; 62.87,6.6 62.91,6.64 U10.1
  TOP w0.508: C130.1 R172.1 R173.1 66.92,5.33 D11.C
UNNAMED_2_CAP_I385_N2: length 13.1
  TOP w0.305: 63.36,14.61 63.56,14.41 ; 63.36,14.61 63.75,14.61 ; 63.36,14.61 62.23,14.61 61.21,13.59 P37.1 ; 63.56,14.41 63.75,14.61 ; 63.56,14.41 U10.7 ; 63.75,14.61 C131.2 U10.6
  TOP w0.508: C131.2 R174.1
UNNAMED_2_DIO_I282_N: length 2
  BOTTOM w0.508: D3.C D4.A
UNNAMED_2_FERRITE_I316_N1: length 1.8
  BOTTOM w0.508: R124.2 32.26,6.76 E4.1
UNNAMED_2_LINLTC4415_I130_CLIM1: length 2.6
  TOP w0.127: U4.4 47.81,18.93 R9.2
UNNAMED_2_LINLTC4415_I130_CLIM2: length 2.7
  TOP w0.127: U4.5 47.31,18.54 46.86,18.99 R10.2
UNNAMED_2_LINLTC4415_I130_EN2N: length 10.7
  TOP w0.127: JP1.2 50.16,21.08 49.72,21.53 46.61,21.53 46.1,21.02 46.1,18.67 46.81,17.96 U4.6
UNNAMED_2_LINLTC4415_I130_STAT1N: length 2.7
  TOP w0.127: R15.1 48.31,10.93 U4.14
UNNAMED_2_LINLTC4415_I130_STAT2N: length 2.7
  TOP w0.127: U4.11 46.81,10.93 R16.1
UNNAMED_2_LINLTC4415_I130_WARN1N: length 2.4
  TOP w0.127: R14.1 48.13,10.54 47.81,10.86 U4.13
UNNAMED_2_LINLTC4415_I130_WARN2N: length 2.4
  TOP w0.127: U4.12 47.31,10.86 46.99,10.54 R13.1
UNNAMED_2_NC2P_I395_N2: length 1.2
  TOP w0.305: R172.2 61.22,7.82 P37.2
UNNAMED_3_ADMAX32690_I367_P0_6: length 72.9
  TOP w0.127: v1(67.06,47.37) 67.05,47.38 66.37,47.38 R48.2
  L2_GND w0.102: v2(101.65,27) 101.65,26.53 100.23,25.11 v3(100.23,24.99)
  L3_SIG w0.089: v3(100.23,24.99) 96.58,21.34 92.3,21.34 88.46,17.49 88.46,16.38 86.68,14.61 79.85,14.61 79.28,14.03 70.74,14.03 67.06,17.72 v1(67.06,27.3)
  L8_SIG w0.089: v1(67.06,27.3) v1(67.06,47.37)
UNNAMED_3_ADMAX32690_I367_P0_7: length 35.5
  TOP w0.127: R53.2 v1(117.54,11.3)
  L2_GND w0.102: v3(100.77,26.04) 101.3,26.56 v2(101.3,27)
  L3_SIG w0.089: v3(100.77,26.04) 100.9,25.91 100.9,23.62 100.46,23.18 100.46,22.1 100.58,21.97 v1(100.58,21.21) ; v1(117.54,11.3) 116.55,10.32 101.41,10.32 v1(100.96,10.76)
  L8_SIG w0.089: v1(100.58,21.21) 100.01,20.64 100.01,11.72 v1(100.96,10.76)
UNNAMED_3_ADMAX32690_I367_P0_9: length 66.1
  TOP w0.127: v1(69.62,47.38) 68.91,47.38 R21.2 ; U1.G1 101.65,25.86 102.74,24.77 102.74,21.62 100.74,19.62 95.5,19.62 94.42,18.54 91.69,18.54 v1(90.11,16.95)
  BOTTOM w0.127: v1(90.11,16.95) 89.28,16.13 86.87,16.13 82.07,20.92 76.58,20.92 70.48,27.02 70.48,46.51 v1(69.62,47.38)
UNNAMED_3_ADMAX32690_I367_P0_10: length 41.1
  TOP w0.127: R30.2 v1(121.35,11.3)
  L3_SIG w0.089: v1(101.09,21.91) 100.71,22.29 100.71,23.05 101.16,23.5 101.16,25.5 101.3,25.64 v3(101.3,27.35) ; v1(100.14,10.73) 100.42,10.73 101.16,10 120.05,10 v1(121.35,11.3)
  L8_SIG w0.089: v1(100.14,10.73) 99.63,11.24 99.63,20.83 100.71,21.91 v1(101.09,21.91)
UNNAMED_3_ADMAX32690_I367_P0_11: length 16.8
  TOP w0.102: 100.14,26.42 100.25,26.52 U1.C1
  TOP w0.127: R31.2 88.82,16.23 91.44,18.86 94.11,18.86 97.09,21.84 97.09,23.37 100.14,26.42
UNNAMED_3_ADMAX32690_I367_P0_13: length 18.2
  TOP w0.127: U1.A3 99.36,27.35 96.27,24.26 93.79,24.26 87.95,18.41 R24.2
UNNAMED_3_ADMAX32690_I367_P0_14: length 13.2
  L3_SIG w0.089: v3(100.25,28.4) 98.19,28.4 97.98,28.19 95.19,28.19 92.58,25.59 v1(92.27,25.59)
  BOTTOM w0.127: v1(92.27,25.59) 91.95,25.27 R18.2
UNNAMED_3_ADMAX32690_I367_P0_16: length 25.9
  TOP w0.127: R56.2 81.74,15.4 v1(82.3,15.4)
  L3_SIG w0.089: v3(100.6,27.35) 100.6,27.19 100.2,26.8 100.2,25.4 96.42,21.62 92.14,21.62 88.17,17.65 88.17,16.54 86.52,14.89 82.8,14.89 v1(82.3,15.4)
UNNAMED_3_ADMAX32690_I367_P0_17: length 23.6
  TOP w0.127: R55.2 82.17,16.99 82.3,16.86 v1(82.3,16.64)
  L2_GND w0.102: v2(100.25,27) 100.25,26.84 v3(99.63,26.23)
  L3_SIG w0.089: v1(82.3,16.64) 82.68,16.26 85.41,16.26 91.66,22.51 95.98,22.51 99.38,25.91 99.38,25.97 v3(99.63,26.23)
UNNAMED_3_ADMAX32690_I367_P0_18: length 28.3
  TOP w0.127: R57.2 116.86,32.51 v1(116.14,32.51)
  L5_PWR w0.102: v5(101.65,28.4) 102.43,27.62 103.19,27.62 104.33,26.48 104.33,25.06 105.47,23.91 105.47,22.61 v1(105.66,22.42)
  BOTTOM w0.127: v1(105.66,22.42) 105.82,22.57 113.25,22.57 114.55,23.88 114.55,32.04 115.03,32.51 v1(116.14,32.51)
UNNAMED_3_ADMAX32690_I367_P0_19: length 18.7
  TOP w0.127: v1(87.5,16.95) 87.5,16.36 R54.2
  L2_GND w0.102: v2(100.6,27) 100.6,26.75 v3(99.63,25.78)
  L3_SIG w0.089: v3(99.63,25.78) 96.04,22.19 91.82,22.19 87.5,17.87 v1(87.5,16.95)
UNNAMED_3_ADMAX32690_I367_P0_20: length 29.9
  TOP w0.127: v1(116.14,33.66) 116.8,33.66 116.86,33.72 R32.2
  L5_PWR w0.102: v5(101.3,28.4) 101,28.1 101,27.53 101.66,26.86 102.49,26.86 103.38,25.97 103.38,24.13 v1(105.09,22.42)
  BOTTOM w0.127: v1(116.14,33.66) 116.14,33.12 115.89,32.86 114.87,32.86 114.17,32.16 114.17,24 113.09,22.92 105.6,22.92 v1(105.09,22.42)
UNNAMED_3_ADMAX32690_I367_P0_21: length 32.8
  TOP w0.127: R22.2 v1(85.01,12.81)
  L4_GND w0.102: v1(99.28,22.1) 99.69,22.51 99.69,23.81 101.47,25.59 101.47,27.52 v4(101.3,27.7)
  L8_SIG w0.089: v1(99.19,12.8) 99.28,12.89 v1(99.28,22.1)
  BOTTOM w0.127: v1(99.19,12.8) 99.18,12.81 v1(85.01,12.81)
UNNAMED_3_ADMAX32690_I367_P0_22: length 25.6
  TOP w0.127: v1(94.81,26.23) 94.36,25.78 94.36,25.43 88.11,19.18 82.9,19.18 82.14,18.41 R29.2
  L5_PWR w0.102: v1(94.81,26.23) 94.96,26.07 99.5,26.07 100.14,26.7 100.14,28.54 100.62,29.02 101.03,29.02 v5(101.3,28.75)
UNNAMED_3_ADMAX32690_I367_P0_23: length 46.6
  TOP w0.127: R49.2 85.41,16.95 85.95,16.41 v1(85.95,13.4)
  L5_PWR w0.102: v1(104.62,28.07) 103.95,28.07 103.63,28.38 102.81,28.38 102.17,29.02 101.92,29.02 v5(101.65,28.75)
  L8_SIG w0.089: v1(104.62,28.07) 104.58,28.07 104.27,27.75 104.27,13.21 105,12.48 106.14,12.48 v1(106.55,12.07)
  BOTTOM w0.127: v1(106.55,12.07) 106.14,12.48 102.93,12.48 102.01,13.4 v1(85.95,13.4)
UNNAMED_3_ADMAX32690_I367_P0_24: length 16.5
  TOP w0.127: v1(116.14,26.07) 116.36,26.29 R159.2
  L4_GND w0.102: v4(102,29.1) 102.27,29.37 102.77,29.37 104.46,27.69 106.49,27.69 106.93,27.24 111.22,27.24 112.4,26.07 v1(116.14,26.07)
UNNAMED_3_ADMAX32690_I367_P0_25: length 16.3
  TOP w0.127: R162.2 116.36,25.02 v1(116.14,25.24)
  L4_GND w0.102: v4(102.35,29.1) 102.66,29.1 104.33,27.43 106.3,27.43 106.81,26.92 111.06,26.92 112.74,25.24 v1(116.14,25.24)
UNNAMED_3_ADMAX32690_I367_P0_26: length 62
  TOP w0.127: v1(116.14,35.24) 120.78,35.24 123.95,38.42 123.95,41.08 129.48,46.61 138.05,46.61 140.4,48.96 140.4,50.67 141.03,51.31 R160.2
  L4_GND w0.102: v4(101.65,27.7) 101.79,27.56 101.79,25.59 103.28,24.1 106.2,24.1 v1(106.36,23.94)
  BOTTOM w0.127: v1(116.14,35.24) 113.44,32.54 113.44,29.78 112.97,29.31 112.97,24.54 112.01,23.59 107.98,23.59 107.25,24.32 106.74,24.32 v1(106.36,23.94)
UNNAMED_3_ADMAX32690_I367_P0_27: length 59.5
  TOP w0.127: R163.2 140.78,48.77 138.24,46.23 129.6,46.23 124.27,40.89 124.27,38.23 120.71,34.67 v1(116.14,34.67)
  L4_GND w0.102: v4(102,27.7) 102.11,27.59 102.11,25.65 103.41,24.35 106.58,24.35 v1(107,23.94)
  BOTTOM w0.127: v1(107,23.94) 107.7,23.24 112.14,23.24 113.32,24.42 113.32,29.15 113.78,29.61 113.78,32.31 v1(116.14,34.67)
UNNAMED_3_ADMAX32690_I367_P0_28: length 66.9
  TOP w0.127: v1(130.18,26.35) 130.18,25.4 127.95,23.18 105.57,23.18 105.44,23.05 v1(105.09,23.05) ; R161.2 v1(141.22,50.04)
  L5_PWR w0.102: v1(105.09,23.05) 103.7,24.45 103.7,26.16 102.74,27.11 101.92,27.11 101.3,27.73 v5(101.3,28.05)
  BOTTOM w0.127: v1(141.22,50.04) 141.67,49.59 141.67,48.58 141,47.91 135.86,47.91 129.79,41.85 129.79,26.73 v1(130.18,26.35)
UNNAMED_3_ADMAX32690_I367_P0_29: length 62.6
  TOP w0.127: R164.2 v1(141.22,47.5) ; v1(130.18,26.92) 129.73,26.48 129.73,25.53 127.7,23.5 105.54,23.5 105.41,23.62 v1(105.09,23.62)
  L5_PWR w0.102: v5(101.65,28.05) 101.65,27.83 102.11,27.37 103,27.37 104.01,26.35 104.01,24.7 v1(105.09,23.62)
  BOTTOM w0.127: v1(130.18,26.92) 130.11,26.99 130.11,41.59 136.02,47.5 v1(141.22,47.5)
UNNAMED_3_ADMAX32690_I367_P0_30: length 21.4
  TOP w0.127: U1.K1 102.7,26.11 103.7,25.11 103.7,21.21 104.84,20.07 105.35,20.07 105.6,20.32 105.6,21.78 106.24,22.42 R20.2
UNNAMED_3_ADMAX32690_I367_P1: length 56.5
  TOP w0.127: R58.2 v1(133.6,13.91)
  L3_SIG w0.089: v1(133.6,13.91) 133.1,13.4 129.79,13.4 125.79,9.4 v1(100.14,9.4)
  L4_GND w0.102: v4(100.95,28.05) 100.58,27.69 100.58,25.72 98.42,23.56 v1(98.42,22.1)
  L8_SIG w0.089: v1(100.14,9.4) 100.14,9.84 98.49,11.49 98.49,22.03 v1(98.42,22.1)
UNNAMED_3_ADMAX32690_I367_P1_1: length 68.6
  TOP w0.127: R59.2 v1(133.6,8.83)
  L3_SIG w0.089: v1(133.6,8.83) 131.25,6.48 93.98,6.48 v1(93.6,6.86)
  L4_GND w0.102: v4(100.6,28.05) 100.33,27.78 100.33,26.48 97.73,23.88 96.17,23.88 v1(95.31,24.73)
  L8_SIG w0.089: v1(93.6,6.86) 95.06,8.32 95.06,10.19 95.38,10.51 95.38,24.67 v1(95.31,24.73)
UNNAMED_3_ADMAX32690_I367_P1_2: length 79.6
  TOP w0.127: R60.2 133.73,3.75 133.6,3.87 v1(133.6,5.46)
  L2_GND w0.102: v3(98.27,27.21) 99.16,27.21 99.65,27.7 v2(99.9,27.7)
  L3_SIG w0.089: v1(133.6,5.46) 90.3,5.46 v1(86.55,9.21) ; v3(98.27,27.21) 97.82,27.21 97.28,26.67 97.28,25.72 95.63,24.07 89.41,24.07 v1(86.55,21.21)
  L8_SIG w0.089: v1(86.55,21.21) v1(86.55,9.21)
UNNAMED_3_ADMAX32690_I367_P1_3: length 50.7
  TOP w0.127: R63.2 v1(128.21,28.38)
  L4_GND w0.102: v4(100.95,27.7) 101.09,27.56 101.09,25.72 98.9,23.53 v1(98.9,21.21)
  L8_SIG w0.089: v1(98.9,21.21) 98.93,21.18 v1(98.93,15.94)
  BOTTOM w0.127: v1(128.21,28.38) 128.21,26.73 123.63,22.16 123.63,18.99 120.59,15.94 v1(98.93,15.94)
UNNAMED_3_ADMAX32690_I367_P1_4: length 66.3
  TOP w0.127: R61.2 v1(136.14,17.21)
  L2_GND w0.102: v2(99.9,28.05) 99.55,28.05 99.19,27.69 v3(97.6,27.69)
  L3_SIG w0.089: v1(95.5,10.03) 100.58,10.03 100.9,9.72 123.51,9.72 127.89,14.1 132.46,14.1 133.48,15.11 135.25,15.11 136.14,16 v1(136.14,17.21) ; v1(95.76,25.08) 96.65,25.97 96.65,26.73 v3(97.6,27.69)
  L8_SIG w0.089: v1(95.76,25.08) 95.76,10.29 v1(95.5,10.03)
UNNAMED_3_ADMAX32690_I367_P1_5: length 59
  TOP w0.102: 99.41,26.86 U1.A2
  TOP w0.127: v1(93.31,23.18) 94.11,23.97 96.36,23.97 99.25,26.86 99.41,26.86 ; R62.2 v1(128.21,31.31)
  L8_SIG w0.089: v1(93.31,23.18) v1(93.31,20.13)
  BOTTOM w0.127: v1(93.31,20.13) 93.98,19.46 93.98,17.4 94.68,16.7 120.33,16.7 122.87,19.24 122.87,24.96 127.76,29.84 127.76,30.86 v1(128.21,31.31)
UNNAMED_3_ADMAX32690_I367_P1_7: length 8.4
  TOP w0.127: v1(92.33,31.24) 93.03,30.54 97.41,30.54 97.8,30.15 U1.A11
  BOTTOM w0.127: R65.2 v1(92.33,31.24)
UNNAMED_3_ADMAX32690_I367_P1_9: length 74.9
  TOP w0.127: R34.2 v1(133.6,6.29)
  L3_SIG w0.089: v1(88.2,22.26) 89.76,23.81 95.76,23.81 98.33,26.38 98.33,26.7 99.68,28.05 v3(100.25,28.05) ; v1(91.5,6.86) 92.52,6.86 93.6,5.78 133.1,5.78 v1(133.6,6.29)
  L8_SIG w0.089: v1(88.2,22.26) 88.2,12.57 91.5,9.27 v1(91.5,6.86)
UNNAMED_3_ADMAX32690_I367_P1_10: length 62.4
  TOP w0.127: R33.2 v1(133.6,11.37)
  L3_SIG w0.089: v3(100.25,27.7) 100.06,27.7 98.84,26.48 98.84,26.13 95.88,23.18 v1(94.87,23.18) ; v1(133.6,11.37) 133.35,11.37 132.52,10.54 127.83,10.54 125.98,8.7 95.35,8.7 v1(94.61,9.43)
  L8_SIG w0.089: v1(94.61,9.43) 94.61,10.32 94.87,10.57 v1(94.87,23.18)
